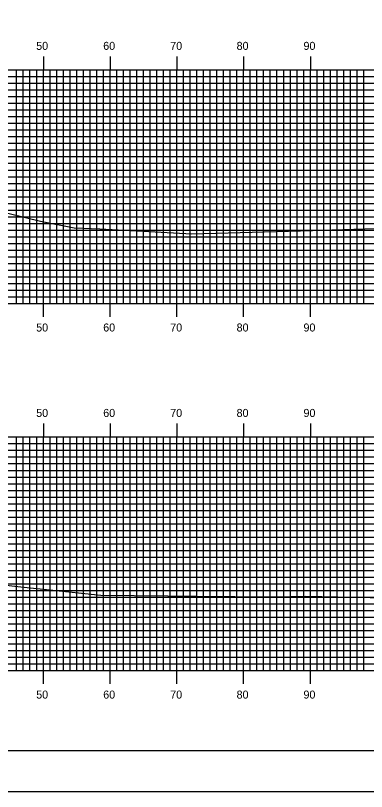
# Model space of a CAD drawing. Extents: x 851753 to 852097, y 364661 to 364881.
# Drawn here: x 851965.1 to 852017.6, y 364661.3 to 364777.5 of the extents above; entities that cross this region are included whole.
import ezdxf

# ---------------------------------------------------------------- set-up
doc = ezdxf.new("R2010")
doc.units = 0
for name, color, linetype in [('BORDER', 7, 'Continuous'), ('H_V ANNOTATION', 7, 'Continuous'), ('MAJOR', 7, 'Continuous'), ('MINOR', 7, 'Continuous'), ('PLOT BOUNDARY', 7, 'Continuous'), ('S_Roadway_Centerline', 7, 'Continuous')]:
    doc.layers.add(name, color=color, linetype=linetype)

msp = doc.modelspace()

# ---------------------------------------------------------------- linework, layer by layer
at = {"layer": 'BORDER'}
msp.add_lwpolyline([(851769.64, 364667.37), (852089.64, 364667.37), (852089.64, 364877.37), (851769.64, 364877.37)], close=True, dxfattribs=at)
at = {"layer": 'MAJOR'}
for p, q in [((851969.24, 364771.37), (851969.24, 364769.37)), ((851979.24, 364771.37), (851979.24, 364769.37)), ((851989.24, 364771.37), (851989.24, 364769.37)), ((851999.24, 364771.37), (851999.24, 364769.37)), ((852009.24, 364771.37), (852009.24, 364769.37)), ((851779.24, 364769.37), (852059.24, 364769.37)), ((851779.24, 364769.37), (852059.24, 364769.37)), ((851969.24, 364734.37), (851969.24, 364769.37)), ((851979.24, 364734.37), (851979.24, 364769.37)), ((851989.24, 364734.37), (851989.24, 364769.37)), ((851999.24, 364734.37), (851999.24, 364769.37)), ((852009.24, 364734.37), (852009.24, 364769.37)), ((851779.24, 364764.37), (852059.24, 364764.37)), ((851779.24, 364759.37), (852059.24, 364759.37)), ((851779.24, 364754.37), (852059.24, 364754.37)), ((851779.24, 364749.37), (852059.24, 364749.37)), ((851779.24, 364744.37), (852059.24, 364744.37)), ((851779.24, 364739.37), (852059.24, 364739.37)), ((851779.24, 364734.37), (852059.24, 364734.37)), ((851779.24, 364734.37), (852059.24, 364734.37)), ((851969.24, 364732.37), (851969.24, 364734.37)), ((851979.24, 364732.37), (851979.24, 364734.37)), ((851989.24, 364732.37), (851989.24, 364734.37)), ((851999.24, 364732.37), (851999.24, 364734.37)), ((852009.24, 364732.37), (852009.24, 364734.37)), ((851969.24, 364716.37), (851969.24, 364714.37)), ((851979.24, 364716.37), (851979.24, 364714.37)), ((851989.24, 364716.37), (851989.24, 364714.37)), ((851999.24, 364716.37), (851999.24, 364714.37)), ((852009.24, 364716.37), (852009.24, 364714.37)), ((851779.24, 364714.37), (852059.24, 364714.37)), ((851779.24, 364714.37), (852059.24, 364714.37)), ((851969.24, 364679.37), (851969.24, 364714.37)), ((851979.24, 364679.37), (851979.24, 364714.37)), ((851989.24, 364679.37), (851989.24, 364714.37)), ((851999.24, 364679.37), (851999.24, 364714.37)), ((852009.24, 364679.37), (852009.24, 364714.37)), ((851779.24, 364709.37), (852059.24, 364709.37)), ((851779.24, 364704.37), (852059.24, 364704.37)), ((851779.24, 364699.37), (852059.24, 364699.37)), ((851779.24, 364694.37), (852059.24, 364694.37)), ((851779.24, 364689.37), (852059.24, 364689.37)), ((851779.24, 364684.37), (852059.24, 364684.37)), ((851779.24, 364679.37), (852059.24, 364679.37)), ((851779.24, 364679.37), (852059.24, 364679.37)), ((851969.24, 364677.37), (851969.24, 364679.37)), ((851979.24, 364677.37), (851979.24, 364679.37)), ((851989.24, 364677.37), (851989.24, 364679.37)), ((851999.24, 364677.37), (851999.24, 364679.37)), ((852009.24, 364677.37), (852009.24, 364679.37))]:
    msp.add_line(p, q, dxfattribs=at)
at = {"layer": 'MINOR'}
for p, q in [((851779.24, 364768.37), (852059.24, 364768.37)), ((851965.24, 364734.37), (851965.24, 364769.37)), ((851966.24, 364734.37), (851966.24, 364769.37)), ((851967.24, 364734.37), (851967.24, 364769.37)), ((851968.24, 364734.37), (851968.24, 364769.37)), ((851970.24, 364734.37), (851970.24, 364769.37)), ((851971.24, 364734.37), (851971.24, 364769.37)), ((851972.24, 364734.37), (851972.24, 364769.37)), ((851973.24, 364734.37), (851973.24, 364769.37)), ((851974.24, 364734.37), (851974.24, 364769.37)), ((851975.24, 364734.37), (851975.24, 364769.37)), ((851976.24, 364734.37), (851976.24, 364769.37)), ((851977.24, 364734.37), (851977.24, 364769.37)), ((851978.24, 364734.37), (851978.24, 364769.37)), ((851980.24, 364734.37), (851980.24, 364769.37)), ((851981.24, 364734.37), (851981.24, 364769.37)), ((851982.24, 364734.37), (851982.24, 364769.37)), ((851983.24, 364734.37), (851983.24, 364769.37)), ((851984.24, 364734.37), (851984.24, 364769.37)), ((851985.24, 364734.37), (851985.24, 364769.37)), ((851986.24, 364734.37), (851986.24, 364769.37)), ((851987.24, 364734.37), (851987.24, 364769.37)), ((851988.24, 364734.37), (851988.24, 364769.37)), ((851990.24, 364734.37), (851990.24, 364769.37)), ((851991.24, 364734.37), (851991.24, 364769.37)), ((851992.24, 364734.37), (851992.24, 364769.37)), ((851993.24, 364734.37), (851993.24, 364769.37)), ((851994.24, 364734.37), (851994.24, 364769.37)), ((851995.24, 364734.37), (851995.24, 364769.37)), ((851996.24, 364734.37), (851996.24, 364769.37)), ((851997.24, 364734.37), (851997.24, 364769.37)), ((851998.24, 364734.37), (851998.24, 364769.37)), ((852000.24, 364734.37), (852000.24, 364769.37)), ((852001.24, 364734.37), (852001.24, 364769.37)), ((852002.24, 364734.37), (852002.24, 364769.37)), ((852003.24, 364734.37), (852003.24, 364769.37)), ((852004.24, 364734.37), (852004.24, 364769.37)), ((852005.24, 364734.37), (852005.24, 364769.37)), ((852006.24, 364734.37), (852006.24, 364769.37)), ((852007.24, 364734.37), (852007.24, 364769.37)), ((852008.24, 364734.37), (852008.24, 364769.37)), ((852010.24, 364734.37), (852010.24, 364769.37)), ((852011.24, 364734.37), (852011.24, 364769.37)), ((852012.24, 364734.37), (852012.24, 364769.37)), ((852013.24, 364734.37), (852013.24, 364769.37)), ((852014.24, 364734.37), (852014.24, 364769.37)), ((852015.24, 364734.37), (852015.24, 364769.37)), ((852016.24, 364734.37), (852016.24, 364769.37)), ((852017.24, 364734.37), (852017.24, 364769.37)), ((851779.24, 364767.37), (852059.24, 364767.37)), ((851779.24, 364766.37), (852059.24, 364766.37)), ((851779.24, 364765.37), (852059.24, 364765.37)), ((851779.24, 364763.37), (852059.24, 364763.37)), ((851779.24, 364762.37), (852059.24, 364762.37)), ((851779.24, 364761.37), (852059.24, 364761.37)), ((851779.24, 364760.37), (852059.24, 364760.37)), ((851779.24, 364758.37), (852059.24, 364758.37)), ((851779.24, 364757.37), (852059.24, 364757.37)), ((851779.24, 364756.37), (852059.24, 364756.37)), ((851779.24, 364755.37), (852059.24, 364755.37)), ((851779.24, 364753.37), (852059.24, 364753.37)), ((851779.24, 364752.37), (852059.24, 364752.37)), ((851779.24, 364751.37), (852059.24, 364751.37)), ((851779.24, 364750.37), (852059.24, 364750.37)), ((851779.24, 364748.37), (852059.24, 364748.37)), ((851779.24, 364747.37), (852059.24, 364747.37)), ((851779.24, 364746.37), (852059.24, 364746.37)), ((851779.24, 364745.37), (852059.24, 364745.37)), ((851779.24, 364743.37), (852059.24, 364743.37)), ((851779.24, 364742.37), (852059.24, 364742.37)), ((851779.24, 364741.37), (852059.24, 364741.37)), ((851779.24, 364740.37), (852059.24, 364740.37)), ((851779.24, 364738.37), (852059.24, 364738.37)), ((851779.24, 364737.37), (852059.24, 364737.37)), ((851779.24, 364736.37), (852059.24, 364736.37)), ((851779.24, 364735.37), (852059.24, 364735.37)), ((851965.24, 364679.37), (851965.24, 364714.37)), ((851966.24, 364679.37), (851966.24, 364714.37)), ((851967.24, 364679.37), (851967.24, 364714.37)), ((851968.24, 364679.37), (851968.24, 364714.37)), ((851970.24, 364679.37), (851970.24, 364714.37)), ((851971.24, 364679.37), (851971.24, 364714.37)), ((851972.24, 364679.37), (851972.24, 364714.37)), ((851973.24, 364679.37), (851973.24, 364714.37)), ((851974.24, 364679.37), (851974.24, 364714.37)), ((851975.24, 364679.37), (851975.24, 364714.37)), ((851976.24, 364679.37), (851976.24, 364714.37)), ((851977.24, 364679.37), (851977.24, 364714.37)), ((851978.24, 364679.37), (851978.24, 364714.37)), ((851980.24, 364679.37), (851980.24, 364714.37)), ((851981.24, 364679.37), (851981.24, 364714.37)), ((851982.24, 364679.37), (851982.24, 364714.37)), ((851983.24, 364679.37), (851983.24, 364714.37)), ((851984.24, 364679.37), (851984.24, 364714.37)), ((851985.24, 364679.37), (851985.24, 364714.37)), ((851986.24, 364679.37), (851986.24, 364714.37)), ((851987.24, 364679.37), (851987.24, 364714.37)), ((851988.24, 364679.37), (851988.24, 364714.37)), ((851990.24, 364679.37), (851990.24, 364714.37)), ((851991.24, 364679.37), (851991.24, 364714.37)), ((851992.24, 364679.37), (851992.24, 364714.37)), ((851993.24, 364679.37), (851993.24, 364714.37)), ((851994.24, 364679.37), (851994.24, 364714.37)), ((851995.24, 364679.37), (851995.24, 364714.37)), ((851996.24, 364679.37), (851996.24, 364714.37)), ((851997.24, 364679.37), (851997.24, 364714.37)), ((851998.24, 364679.37), (851998.24, 364714.37)), ((852000.24, 364679.37), (852000.24, 364714.37)), ((852001.24, 364679.37), (852001.24, 364714.37)), ((852002.24, 364679.37), (852002.24, 364714.37)), ((852003.24, 364679.37), (852003.24, 364714.37)), ((852004.24, 364679.37), (852004.24, 364714.37)), ((852005.24, 364679.37), (852005.24, 364714.37)), ((852006.24, 364679.37), (852006.24, 364714.37)), ((852007.24, 364679.37), (852007.24, 364714.37)), ((852008.24, 364679.37), (852008.24, 364714.37)), ((852010.24, 364679.37), (852010.24, 364714.37)), ((852011.24, 364679.37), (852011.24, 364714.37)), ((852012.24, 364679.37), (852012.24, 364714.37)), ((852013.24, 364679.37), (852013.24, 364714.37)), ((852014.24, 364679.37), (852014.24, 364714.37)), ((852015.24, 364679.37), (852015.24, 364714.37)), ((852016.24, 364679.37), (852016.24, 364714.37)), ((852017.24, 364679.37), (852017.24, 364714.37)), ((851779.24, 364713.37), (852059.24, 364713.37)), ((851779.24, 364712.37), (852059.24, 364712.37)), ((851779.24, 364711.37), (852059.24, 364711.37)), ((851779.24, 364710.37), (852059.24, 364710.37)), ((851779.24, 364708.37), (852059.24, 364708.37)), ((851779.24, 364707.37), (852059.24, 364707.37)), ((851779.24, 364706.37), (852059.24, 364706.37)), ((851779.24, 364705.37), (852059.24, 364705.37)), ((851779.24, 364703.37), (852059.24, 364703.37)), ((851779.24, 364702.37), (852059.24, 364702.37)), ((851779.24, 364701.37), (852059.24, 364701.37)), ((851779.24, 364700.37), (852059.24, 364700.37)), ((851779.24, 364698.37), (852059.24, 364698.37)), ((851779.24, 364697.37), (852059.24, 364697.37)), ((851779.24, 364696.37), (852059.24, 364696.37)), ((851779.24, 364695.37), (852059.24, 364695.37)), ((851779.24, 364693.37), (852059.24, 364693.37)), ((851779.24, 364692.37), (852059.24, 364692.37)), ((851779.24, 364691.37), (852059.24, 364691.37)), ((851779.24, 364690.37), (852059.24, 364690.37)), ((851779.24, 364688.37), (852059.24, 364688.37)), ((851779.24, 364687.37), (852059.24, 364687.37)), ((851779.24, 364686.37), (852059.24, 364686.37)), ((851779.24, 364685.37), (852059.24, 364685.37)), ((851779.24, 364683.37), (852059.24, 364683.37)), ((851779.24, 364682.37), (852059.24, 364682.37)), ((851779.24, 364681.37), (852059.24, 364681.37)), ((851779.24, 364680.37), (852059.24, 364680.37))]:
    msp.add_line(p, q, dxfattribs=at)
at = {"layer": 'PLOT BOUNDARY'}
msp.add_lwpolyline([(851753.46, 364661.25), (852093.46, 364661.25), (852093.46, 364881.25), (851753.46, 364881.25)], close=True, dxfattribs=at)
at = {"layer": 'S_Roadway_Centerline'}
for points in [[(851950.37, 364751.21), (851968.79, 364746.7), (851973.85, 364745.71), (851977.69, 364745.58), (851991.46, 364744.81), (852007.78, 364745.28), (852009.57, 364745.32), (852010.8, 364745.36), (852022.36, 364745.73), (852027.69, 364745.64), (852031.99, 364745.46), (852034.87, 364745.34), (852035.13, 364745.39), (852044.9, 364746.3), (852049.13, 364746.6), (852059.24, 364747.43)], [(851940.2, 364700.18), (851940.49, 364700.08), (851940.56, 364700.06), (851940.95, 364699.91), (851957.44, 364692.86), (851965.87, 364691.92), (851977.86, 364690.69), (851987.91, 364690.56), (851992.17, 364690.5), (852003.7, 364690.4), (852008.58, 364690.52), (852022.99, 364690.23), (852023.93, 364690.19), (852024.96, 364690.42), (852029.08, 364691.28), (852042.76, 364693.52), (852054.82, 364694.96), (852059.24, 364695.34)]]:
    msp.add_lwpolyline(points, dxfattribs=at)

# ---------------------------------------------------------------- texts
at = {"layer": 'H_V ANNOTATION'}
for s, p in [('50', (851968.17, 364772.37)), ('60', (851978.21, 364772.37)), ('70', (851988.25, 364772.37)), ('80', (851998.19, 364772.37)), ('90', (852008.21, 364772.37)), ('50', (851968.17, 364730.17)), ('60', (851978.21, 364730.17)), ('70', (851988.25, 364730.17)), ('80', (851998.19, 364730.17)), ('90', (852008.21, 364730.17)), ('50', (851968.17, 364717.37)), ('60', (851978.21, 364717.37)), ('70', (851988.25, 364717.37)), ('80', (851998.19, 364717.37)), ('90', (852008.21, 364717.37)), ('50', (851968.17, 364675.17)), ('60', (851978.21, 364675.17)), ('70', (851988.25, 364675.17)), ('80', (851998.19, 364675.17)), ('90', (852008.21, 364675.17))]:
    msp.add_text(s, height=1.2, dxfattribs=at).set_placement(p)

doc.saveas('drawing.dxf')
